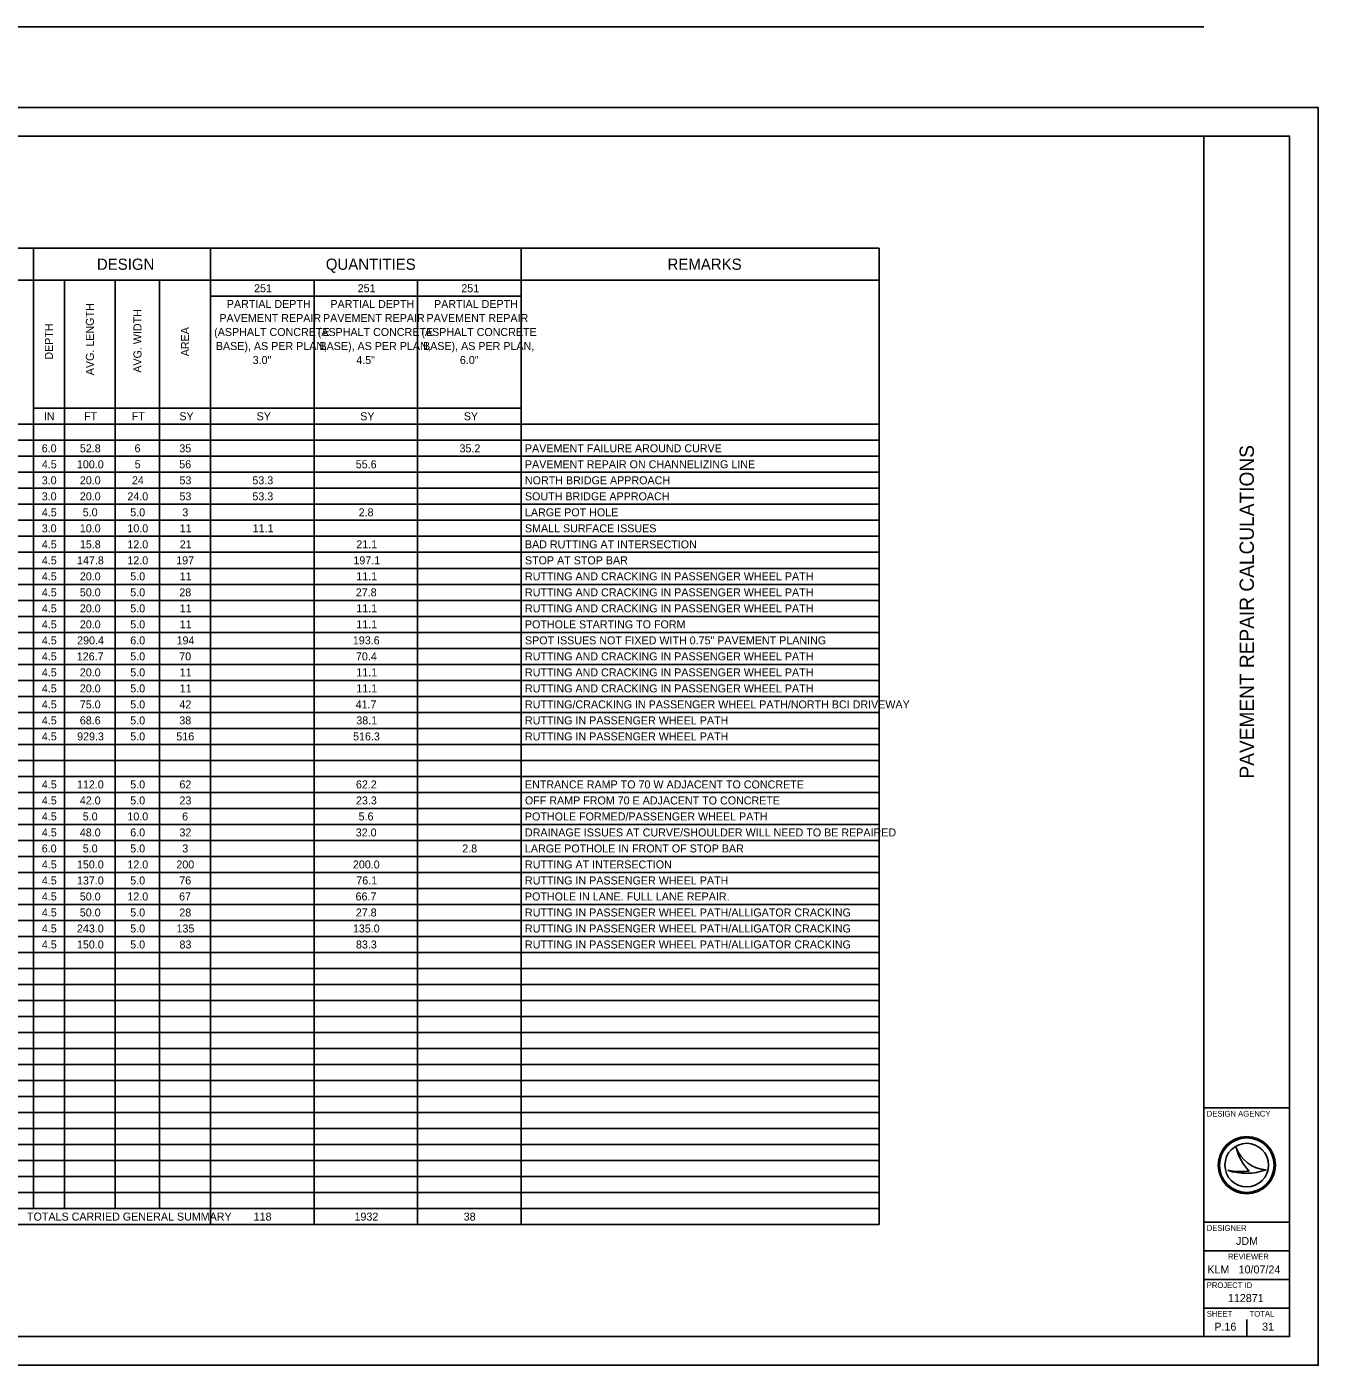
# Model space of a CAD drawing. Extents: x 0 to 34, y 0 to 23.4.
# Drawn here: x 11.41 to 34, y 0 to 23.41 of the extents above; entities that cross this region are included whole.
import ezdxf

# ---------------------------------------------------------------- set-up
doc = ezdxf.new("R2010")
doc.units = 0
for name, color, linetype in [('SH_Border', 7, 'Continuous'), ('SH_Cut_Line', 7, 'Continuous'), ('SH_Data', 7, 'Continuous'), ('SH_Text', 7, 'Continuous')]:
    doc.layers.add(name, color=color, linetype=linetype)

msp = doc.modelspace()

# ---------------------------------------------------------------- linework, layer by layer
at = {"layer": 'SH_Border'}
for p, q in [((32, 0.5), (32, 21.5)), ((32, 4.5), (33.5, 4.5)), ((32, 2.5), (33.5, 2.5)), ((32, 2), (33.5, 2)), ((32, 1.5), (33.5, 1.5)), ((32, 1), (33.5, 1))]:
    msp.add_line(p, q, dxfattribs=at)
msp.add_lwpolyline([(1.5, 21.5), (33.5, 21.5), (33.5, 0.5), (1.5, 0.5)], close=True, dxfattribs=at)
at = {"layer": 'SH_Cut_Line'}
msp.add_lwpolyline([(0, 0), (34, 0), (34, 22), (0, 22)], close=True, dxfattribs=at)
at = {"layer": 'SH_Data'}
for p, q in [((32.567, 3.81), (32.567, 3.81)), ((32.417, 3.41), (32.417, 3.41)), ((32.75, 3.5), (32.75, 3.5)), ((33.087, 3.419), (33.087, 3.419)), ((32.75, 0.5), (32.75, 0.8)), ((32.375, 0.675), (32.375, 0.675))]:
    msp.add_line(p, q, dxfattribs=at)
for radius in [0.5, 0.477, 0.477, 0.382]:
    msp.add_circle((32.75, 3.5), radius, dxfattribs=at)
for centre, radius, start, end in [((33.116, 3.998), 0.58, 198.9257, 198.9319), ((33.347, 3.97), 0.796, 191.6379, 191.6421), ((33.116, 3.998), 0.58, 198.9319, 267.1657), ((33.347, 3.97), 0.796, 191.6421, 226.0947), ((32.739, 4.37), 1.013, 251.4576, 290.0832), ((32.648, 4.654), 1.266, 259.4964, 259.4995), ((32.739, 4.37), 1.013, 251.4527, 251.4576), ((32.648, 4.654), 1.266, 259.4995, 276.6672)]:
    msp.add_arc(centre, radius, start, end, dxfattribs=at)
at = {"layer": 'SH_Text'}
for p, q in [((1.5, 23.414), (32, 23.414)), ((7.181, 19.54), (26.319, 19.54)), ((11.529, 19.54), (11.529, 2.74)), ((14.625, 19.54), (14.625, 2.46)), ((20.061, 19.54), (20.061, 2.46)), ((26.319, 19.54), (26.319, 2.46)), ((7.181, 18.98), (26.319, 18.98)), ((12.072, 18.98), (12.072, 2.74)), ((12.962, 18.98), (12.962, 2.74)), ((13.736, 18.98), (13.736, 2.74)), ((16.437, 18.98), (16.437, 2.74)), ((18.249, 18.98), (18.249, 16.46)), ((14.625, 18.7), (20.061, 18.7)), ((11.529, 16.74), (20.061, 16.74)), ((7.181, 16.46), (26.319, 16.46)), ((18.249, 16.46), (18.249, 2.74)), ((7.181, 16.18), (20.061, 16.18)), ((20.061, 16.18), (26.319, 16.18)), ((7.181, 15.9), (26.319, 15.9)), ((7.181, 15.62), (26.319, 15.62)), ((7.181, 15.34), (26.319, 15.34)), ((7.181, 15.06), (26.319, 15.06)), ((7.181, 14.78), (26.319, 14.78)), ((7.181, 14.5), (26.319, 14.5)), ((7.181, 14.22), (26.319, 14.22)), ((7.181, 13.94), (26.319, 13.94)), ((7.181, 13.66), (26.319, 13.66)), ((7.181, 13.38), (26.319, 13.38)), ((7.181, 13.1), (26.319, 13.1)), ((7.181, 12.82), (26.319, 12.82)), ((7.181, 12.54), (26.319, 12.54)), ((7.181, 12.26), (26.319, 12.26)), ((7.181, 11.98), (26.319, 11.98)), ((7.181, 11.7), (26.319, 11.7)), ((7.181, 11.42), (26.319, 11.42)), ((7.181, 11.14), (26.319, 11.14)), ((7.181, 10.86), (26.319, 10.86)), ((7.181, 10.58), (26.319, 10.58)), ((7.181, 10.3), (26.319, 10.3)), ((7.181, 10.02), (26.319, 10.02)), ((7.181, 9.74), (26.319, 9.74)), ((7.181, 9.46), (26.319, 9.46)), ((7.181, 9.18), (26.319, 9.18)), ((7.181, 8.9), (26.319, 8.9)), ((7.181, 8.62), (26.319, 8.62)), ((7.181, 8.34), (26.319, 8.34)), ((7.181, 8.06), (26.319, 8.06)), ((7.181, 7.78), (26.319, 7.78)), ((7.181, 7.5), (26.319, 7.5)), ((7.181, 7.22), (26.319, 7.22)), ((7.181, 6.94), (26.319, 6.94)), ((7.181, 6.66), (26.319, 6.66)), ((7.181, 6.38), (26.319, 6.38)), ((7.181, 6.1), (26.319, 6.1)), ((7.181, 5.82), (26.319, 5.82)), ((7.181, 5.54), (26.319, 5.54)), ((7.181, 5.26), (26.319, 5.26)), ((7.181, 4.98), (26.319, 4.98)), ((7.181, 4.7), (26.319, 4.7)), ((7.181, 4.42), (26.319, 4.42)), ((7.181, 4.14), (26.319, 4.14)), ((7.181, 3.86), (26.319, 3.86)), ((7.181, 3.58), (26.319, 3.58)), ((7.181, 3.3), (26.319, 3.3)), ((7.181, 3.02), (26.319, 3.02)), ((7.181, 2.74), (26.319, 2.74)), ((16.437, 2.74), (16.437, 2.46)), ((18.249, 2.74), (18.249, 2.46)), ((7.181, 2.46), (26.319, 2.46))]:
    msp.add_line(p, q, dxfattribs=at)

# ---------------------------------------------------------------- texts
at = {"layer": 'SH_Data'}
msp.add_text('PAVEMENT REPAIR CALCULATIONS', height=0.25, rotation=90, dxfattribs=at).set_placement((32.875, 10.263))
for s, height, p in [('DESIGN AGENCY', 0.1, (32.05, 4.35)), ('DESIGNER', 0.1, (32.05, 2.35)), ('JDM', 0.14, (32.562, 2.105)), ('REVIEWER', 0.1, (32.422, 1.85)), ('KLM', 0.14, (32.061, 1.605)), ('10/07/24', 0.14, (32.608, 1.605)), ('PROJECT ID', 0.1, (32.05, 1.35)), ('112871', 0.14, (32.421, 1.105)), ('SHEET', 0.1, (32.05, 0.85)), ('TOTAL', 0.1, (32.8, 0.85)), ('P.16', 0.14, (32.183, 0.605)), ('31', 0.14, (33.019, 0.605))]:
    msp.add_text(s, height=height, dxfattribs=at).set_placement(p)
at = {"layer": 'SH_Text'}
for s, height, p in [('DESIGN', 0.196, (12.64, 19.162)), ('QUANTITIES', 0.196, (16.643, 19.162)), ('REMARKS', 0.196, (22.62, 19.162)), ('251', 0.14, (15.389, 18.77)), ('251', 0.14, (17.201, 18.77)), ('251', 0.14, (19.013, 18.77)), ('PARTIAL DEPTH ', 0.14, (14.912, 18.494)), ('PARTIAL DEPTH ', 0.14, (16.724, 18.494)), ('PARTIAL DEPTH ', 0.14, (18.536, 18.494)), ('PAVEMENT REPAIR ', 0.14, (14.782, 18.249)), ('PAVEMENT REPAIR ', 0.14, (16.594, 18.249)), ('PAVEMENT REPAIR ', 0.14, (18.405, 18.249)), ('(ASPHALT CONCRETE ', 0.14, (14.691, 18.004)), ('(ASPHALT CONCRETE ', 0.14, (16.502, 18.004)), ('(ASPHALT CONCRETE ', 0.14, (18.314, 18.004)), ('BASE), AS PER PLAN, ', 0.14, (14.72, 17.759)), ('BASE), AS PER PLAN, ', 0.14, (16.532, 17.759)), ('BASE), AS PER PLAN, ', 0.14, (18.343, 17.759)), ('3.0"', 0.14, (15.364, 17.514)), ('4.5"', 0.14, (17.176, 17.514)), ('6.0"', 0.14, (18.988, 17.514)), ('IN', 0.14, (11.712, 16.53)), ('FT', 0.14, (12.416, 16.53)), ('FT', 0.14, (13.248, 16.53)), ('SY', 0.14, (14.082, 16.53)), ('SY', 0.14, (15.433, 16.53)), ('SY', 0.14, (17.245, 16.53)), ('SY', 0.14, (19.056, 16.53)), ('6.0', 0.14, (11.675, 15.97)), ('52.8', 0.14, (12.342, 15.97)), ('6', 0.14, (13.298, 15.97)), ('35', 0.14, (14.082, 15.97)), ('35.2', 0.14, (18.982, 15.97)), ('PAVEMENT FAILURE AROUND CURVE', 0.14, (20.126, 15.97)), ('4.5', 0.14, (11.677, 15.69)), ('100.0', 0.14, (12.291, 15.69)), ('5', 0.14, (13.301, 15.69)), ('56', 0.14, (14.08, 15.69)), ('55.6', 0.14, (17.167, 15.69)), ('PAVEMENT REPAIR ON CHANNELIZING LINE', 0.14, (20.126, 15.69)), ('3.0', 0.14, (11.675, 15.41)), ('20.0', 0.14, (12.341, 15.41)), ('24', 0.14, (13.252, 15.41)), ('53', 0.14, (14.084, 15.41)), ('53.3', 0.14, (15.359, 15.41)), ('NORTH BRIDGE APPROACH', 0.14, (20.126, 15.41)), ('3.0', 0.14, (11.675, 15.13)), ('20.0', 0.14, (12.341, 15.13)), ('24.0', 0.14, (13.173, 15.13)), ('53', 0.14, (14.084, 15.13)), ('53.3', 0.14, (15.359, 15.13)), ('SOUTH BRIDGE APPROACH', 0.14, (20.126, 15.13)), ('4.5', 0.14, (11.677, 14.85)), ('5.0', 0.14, (12.392, 14.85)), ('5.0', 0.14, (13.223, 14.85)), ('3', 0.14, (14.134, 14.85)), ('2.8', 0.14, (17.218, 14.85)), ('LARGE POT HOLE', 0.14, (20.126, 14.85)), ('3.0', 0.14, (11.675, 14.57)), ('10.0', 0.14, (12.341, 14.57)), ('10.0', 0.14, (13.173, 14.57)), ('11', 0.14, (14.089, 14.57)), ('11.1', 0.14, (15.364, 14.57)), ('SMALL SURFACE ISSUES', 0.14, (20.126, 14.57)), ('4.5', 0.14, (11.677, 14.29)), ('15.8', 0.14, (12.342, 14.29)), ('12.0', 0.14, (13.173, 14.29)), ('21', 0.14, (14.089, 14.29)), ('21.1', 0.14, (17.176, 14.29)), ('BAD RUTTING AT INTERSECTION', 0.14, (20.126, 14.29)), ('4.5', 0.14, (11.677, 14.01)), ('147.8', 0.14, (12.292, 14.01)), ('12.0', 0.14, (13.173, 14.01)), ('197', 0.14, (14.027, 14.01)), ('197.1', 0.14, (17.126, 14.01)), ('STOP AT STOP BAR', 0.14, (20.126, 14.01)), ('4.5', 0.14, (11.677, 13.73)), ('20.0', 0.14, (12.341, 13.73)), ('5.0', 0.14, (13.223, 13.73)), ('11', 0.14, (14.089, 13.73)), ('11.1', 0.14, (17.176, 13.73)), ('RUTTING AND CRACKING IN PASSENGER WHEEL PATH', 0.14, (20.126, 13.73)), ('4.5', 0.14, (11.677, 13.45)), ('50.0', 0.14, (12.341, 13.45)), ('5.0', 0.14, (13.223, 13.45)), ('28', 0.14, (14.081, 13.45)), ('27.8', 0.14, (17.168, 13.45)), ('RUTTING AND CRACKING IN PASSENGER WHEEL PATH', 0.14, (20.126, 13.45)), ('4.5', 0.14, (11.677, 13.17)), ('20.0', 0.14, (12.341, 13.17)), ('5.0', 0.14, (13.223, 13.17)), ('11', 0.14, (14.089, 13.17)), ('11.1', 0.14, (17.176, 13.17)), ('RUTTING AND CRACKING IN PASSENGER WHEEL PATH', 0.14, (20.126, 13.17)), ('4.5', 0.14, (11.677, 12.89)), ('20.0', 0.14, (12.341, 12.89)), ('5.0', 0.14, (13.223, 12.89)), ('11', 0.14, (14.089, 12.89)), ('11.1', 0.14, (17.176, 12.89)), ('POTHOLE STARTING TO FORM', 0.14, (20.126, 12.89)), ('4.5', 0.14, (11.677, 12.61)), ('290.4', 0.14, (12.294, 12.61)), ('6.0', 0.14, (13.223, 12.61)), ('194', 0.14, (14.033, 12.61)), ('193.6', 0.14, (17.116, 12.61)), ('SPOT ISSUES NOT FIXED WITH 0.75" PAVEMENT PLANING', 0.14, (20.126, 12.61)), ('4.5', 0.14, (11.677, 12.33)), ('126.7', 0.14, (12.288, 12.33)), ('5.0', 0.14, (13.223, 12.33)), ('70', 0.14, (14.08, 12.33)), ('70.4', 0.14, (17.171, 12.33)), ('RUTTING AND CRACKING IN PASSENGER WHEEL PATH', 0.14, (20.126, 12.33)), ('4.5', 0.14, (11.677, 12.05)), ('20.0', 0.14, (12.341, 12.05)), ('5.0', 0.14, (13.223, 12.05)), ('11', 0.14, (14.089, 12.05)), ('11.1', 0.14, (17.176, 12.05)), ('RUTTING AND CRACKING IN PASSENGER WHEEL PATH', 0.14, (20.126, 12.05)), ('4.5', 0.14, (11.677, 11.77)), ('20.0', 0.14, (12.341, 11.77)), ('5.0', 0.14, (13.223, 11.77)), ('11', 0.14, (14.089, 11.77)), ('11.1', 0.14, (17.176, 11.77)), ('RUTTING AND CRACKING IN PASSENGER WHEEL PATH', 0.14, (20.126, 11.77)), ('4.5', 0.14, (11.677, 11.49)), ('75.0', 0.14, (12.341, 11.49)), ('5.0', 0.14, (13.223, 11.49)), ('42', 0.14, (14.083, 11.49)), ('41.7', 0.14, (17.164, 11.49)), ('RUTTING/CRACKING IN PASSENGER WHEEL PATH/NORTH BCI DRIVEWAY', 0.14, (20.126, 11.49)), ('4.5', 0.14, (11.677, 11.21)), ('68.6', 0.14, (12.341, 11.21)), ('5.0', 0.14, (13.223, 11.21)), ('38', 0.14, (14.081, 11.21)), ('38.1', 0.14, (17.176, 11.21)), ('RUTTING IN PASSENGER WHEEL PATH', 0.14, (20.126, 11.21)), ('4.5', 0.14, (11.677, 10.93)), ('929.3', 0.14, (12.294, 10.93)), ('5.0', 0.14, (13.223, 10.93)), ('516', 0.14, (14.029, 10.93)), ('516.3', 0.14, (17.12, 10.93)), ('RUTTING IN PASSENGER WHEEL PATH', 0.14, (20.126, 10.93)), ('4.5', 0.14, (11.677, 10.09)), ('112.0', 0.14, (12.291, 10.09)), ('5.0', 0.14, (13.223, 10.09)), ('62', 0.14, (14.083, 10.09)), ('62.2', 0.14, (17.17, 10.09)), ('ENTRANCE RAMP TO 70 W ADJACENT TO CONCRETE', 0.14, (20.126, 10.09)), ('4.5', 0.14, (11.677, 9.81)), ('42.0', 0.14, (12.341, 9.81)), ('5.0', 0.14, (13.223, 9.81)), ('23', 0.14, (14.084, 9.81)), ('23.3', 0.14, (17.171, 9.81)), ('OFF RAMP FROM 70 E ADJACENT TO CONCRETE', 0.14, (20.126, 9.81)), ('4.5', 0.14, (11.677, 9.53)), ('5.0', 0.14, (12.392, 9.53)), ('10.0', 0.14, (13.173, 9.53)), ('6', 0.14, (14.13, 9.53)), ('5.6', 0.14, (17.217, 9.53)), ('POTHOLE FORMED/PASSENGER WHEEL PATH', 0.14, (20.126, 9.53)), ('4.5', 0.14, (11.677, 9.25)), ('48.0', 0.14, (12.341, 9.25)), ('6.0', 0.14, (13.223, 9.25)), ('32', 0.14, (14.083, 9.25)), ('32.0', 0.14, (17.167, 9.25)), ('DRAINAGE ISSUES AT CURVE/SHOULDER WILL NEED TO BE REPAIRED', 0.14, (20.126, 9.25)), ('6.0', 0.14, (11.675, 8.97)), ('5.0', 0.14, (12.392, 8.97)), ('5.0', 0.14, (13.223, 8.97)), ('3', 0.14, (14.134, 8.97)), ('2.8', 0.14, (19.03, 8.97)), ('LARGE POTHOLE IN FRONT OF STOP BAR', 0.14, (20.126, 8.97)), ('4.5', 0.14, (11.677, 8.69)), ('150.0', 0.14, (12.291, 8.69)), ('12.0', 0.14, (13.173, 8.69)), ('200', 0.14, (14.03, 8.69)), ('200.0', 0.14, (17.117, 8.69)), ('RUTTING AT INTERSECTION', 0.14, (20.126, 8.69)), ('4.5', 0.14, (11.677, 8.41)), ('137.0', 0.14, (12.291, 8.41)), ('5.0', 0.14, (13.223, 8.41)), ('76', 0.14, (14.08, 8.41)), ('76.1', 0.14, (17.176, 8.41)), ('RUTTING IN PASSENGER WHEEL PATH', 0.14, (20.126, 8.41)), ('4.5', 0.14, (11.677, 8.13)), ('50.0', 0.14, (12.341, 8.13)), ('12.0', 0.14, (13.173, 8.13)), ('67', 0.14, (14.077, 8.13)), ('66.7', 0.14, (17.164, 8.13)), ('POTHOLE IN LANE. FULL LANE REPAIR.', 0.14, (20.126, 8.13)), ('4.5', 0.14, (11.677, 7.85)), ('50.0', 0.14, (12.341, 7.85)), ('5.0', 0.14, (13.223, 7.85)), ('28', 0.14, (14.081, 7.85)), ('27.8', 0.14, (17.168, 7.85)), ('RUTTING IN PASSENGER WHEEL PATH/ALLIGATOR CRACKING', 0.14, (20.126, 7.85)), ('4.5', 0.14, (11.677, 7.57)), ('243.0', 0.14, (12.291, 7.57)), ('5.0', 0.14, (13.223, 7.57)), ('135', 0.14, (14.032, 7.57)), ('135.0', 0.14, (17.117, 7.57)), ('RUTTING IN PASSENGER WHEEL PATH/ALLIGATOR CRACKING', 0.14, (20.126, 7.57)), ('4.5', 0.14, (11.677, 7.29)), ('150.0', 0.14, (12.291, 7.29)), ('5.0', 0.14, (13.223, 7.29)), ('83', 0.14, (14.084, 7.29)), ('83.3', 0.14, (17.171, 7.29)), ('RUTTING IN PASSENGER WHEEL PATH/ALLIGATOR CRACKING', 0.14, (20.126, 7.29)), ('TOTALS CARRIED GENERAL SUMMARY', 0.14, (11.418, 2.53)), ('118', 0.14, (15.381, 2.53)), ('1932', 0.14, (17.145, 2.53)), ('38', 0.14, (19.055, 2.53))]:
    msp.add_text(s, height=height, dxfattribs=at).set_placement(p)
for s, p in [('AVG. LENGTH', (12.587, 17.318)), ('AVG. WIDTH', (13.419, 17.362)), ('DEPTH', (11.871, 17.59)), ('AREA', (14.251, 17.65))]:
    msp.add_text(s, height=0.14, rotation=90, dxfattribs=at).set_placement(p)

doc.saveas('drawing.dxf')
